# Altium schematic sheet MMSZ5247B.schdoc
size 127 x 101 mm
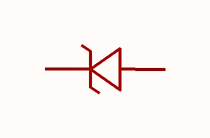
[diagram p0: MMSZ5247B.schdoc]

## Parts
U?  mmsz5247b  [SOD-123_L2.7-W1.6-LS3.7-RD-1]  (value not drawn)

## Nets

Not connected (* = marked no-connect by the designer): U? 1(C) 2(A)

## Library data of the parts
U? = mmsz5247b: 二极管配置:1个独立式;稳压值(标称值):17V;稳压值(范围):16.15V~17.85V;耗散功率(Pd):350mW;; Manufacturer: CJ(江苏长电/长晶); AddInBom: yes; ModelId: 528459655f7d4601a76356f3191c812b; ModelTransform: 151.575,66.929,0,0,0,0,0,0,0; Diode Configuration: 1个独立式; Zener Voltage(Nom): 17V; Reverse Leakage Current (Ir): 100nA@13V; Pd - Power Dissipation: 350mW; Impedance(Zzt): 19Ω; Impedance(Zzk): 600Ω; Operating Junction Temperature Range: -55℃~+150℃; Tolerance: ±5%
